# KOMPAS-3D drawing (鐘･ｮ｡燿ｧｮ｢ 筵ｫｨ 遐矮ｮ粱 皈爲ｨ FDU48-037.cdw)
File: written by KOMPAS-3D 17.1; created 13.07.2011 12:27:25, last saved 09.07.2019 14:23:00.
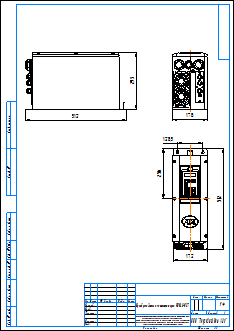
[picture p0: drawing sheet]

Sheet 1: A3, portrait

Title block, sheet 1: name: Преобразователи частоты серии FDU48-037; scale: 1:4; sheets: 1; sheet format: A3; stored path: \\adlc.lan\data\АДЛ_ПКД\3D-модели\Поставщики\Оборудование Emotron\Преобразователи частоты\Серия FDU 2.0\KOMPAS 2D\Преобразователи частоты серии FDU48-037.cdw

Views: Спереди 1
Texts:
  Рама для чертежей
  Лит-Масса-Масштаб
  Материал-Предприятие
  Масштаб
  Изм.
  Лист
  № докум.
  Подп.
  Дата
  Лит.
  Разраб.
  Пров.
  Т.контр.
  Листов
  Внимание! Данный продукт является объектом авторского права ООО «Торговый Дом АДЛ».
  Запрещается изменение, копирование, распространение
  (в том числе путем копирования на другие сайты и ресурсы в Интернете)
  или любое иное использование информации и объектов без предварительного
  согласия правообладателя (ООО «Торговый Дом АДЛ»).
  Н.контр.
  Утв.
  ООО "Торговый дом АДЛ"
  Изменение
  Номер документа
  Подпись
  Обозначение документа
  Наименование изделия
  Масса изделия по ГОСТ 2.109-73
  Порядковый номер листа
  Общее количество листов в документе
  Характер работы, выполненной лицом, подписавшим документ
  Наименование или индекс предприятия, выпускающего документ
  Инв. № подл.
  Подп. и дата
  Взам. инв. №
  Инв. № дубл.
  Инвентарный номер подлинника по ГОСТ 2.501-68
  Подпись принявшего подлинник в отдел технической документации
  Инвентарный номер подлинника, взамен которого выпущен данный подлинник
  Инвентарный номер дубликата по ГОСТ 2.502-68
  Подпись принявшего дубликат в отдел технической документации
  Справ. №
  Перв. примен.
  Обозначение документа, взамен или на основании которого выпущен данный документ
  Обозначение документа, в котором впервые записан данный документ
  Подпись лица, копировавшего чертеж
  Обозначение формата листа
  !Рама для чертежа
Dimensions and other numbers on the sheet: 178; 512; 128,5; 172; 293; 256; 1:4; 1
